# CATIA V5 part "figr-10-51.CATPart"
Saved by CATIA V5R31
Part number: Part1
Bounding box of the stored display mesh (mm): x -68.386 to 32.095, y 0 to 344, z -0.079 to 67.481
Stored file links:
  D:\PROJECTS\Project 2021\US EDITION\CATIA V5 6R 2021\Resources\Part Files\c10_catia_v5_6r2021_prt\c10_catia_v5_6r2021_prt\figr-10-51.CATPart
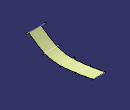
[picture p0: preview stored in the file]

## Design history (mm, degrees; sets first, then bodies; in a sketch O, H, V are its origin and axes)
Body1 (main body)
  Plane1: type Offset, RefPlane zx-plane, Offset 86
  Plane2: type Offset, RefPlane Plane1, Offset 86
  Plane3: type Offset, RefPlane Plane2, Offset 86
  Plane4: type Offset, RefPlane Plane3, Offset 86
  Sketch1 on zx-plane, origin (0, 0, 0), H (-1, 0, 0), V (0, 0, 1)
    line L1 (-32.0954, 67.4806) -> (68.3859, 67.4806)
    horizontal: L1 H
  Sketch2 on Plane1, origin (0, 86, 0), H (-1, 0, 0), V (0, 0, 1)
    line L1 (-24.4409, 14.2252) -> (55.9283, 14.2252)
    horizontal: L1 H
  Sketch3 on Plane2, origin (0, 172, 0), H (-1, 0, 0), V (0, 0, 1)
    line L1 (-24.2042, 0) -> (53.3039, 0)
    point P1 (-24.2042, 0)
    coincidence: P1 H
    horizontal: L1 H
  Sketch4 on Plane3, origin (0, 258, 0), H (-1, 0, 0), V (0, 0, 1)
    line L1 (-23.6533, 8.5985) -> (50.1324, 8.5985)
    horizontal: L1 H
  Sketch5 on Plane4, origin (0, 344, 0), H (-1, 0, 0), V (0, 0, 1)
    line L1 (-20.9465, 23.2339) -> (46.0713, 23.2339)
    horizontal: L1 H
  Sweep1: type Conic, Guide (Sketch1; Sketch2; Sketch3; Sketch4; Sketch5)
